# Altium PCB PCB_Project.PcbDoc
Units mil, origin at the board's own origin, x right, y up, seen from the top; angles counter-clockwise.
Board outline 1574.8 x 1574.8 mil, 2 copper layers (Top Layer, Bottom Layer); 30 components, 25 nets, 151 pads, 12 vias.
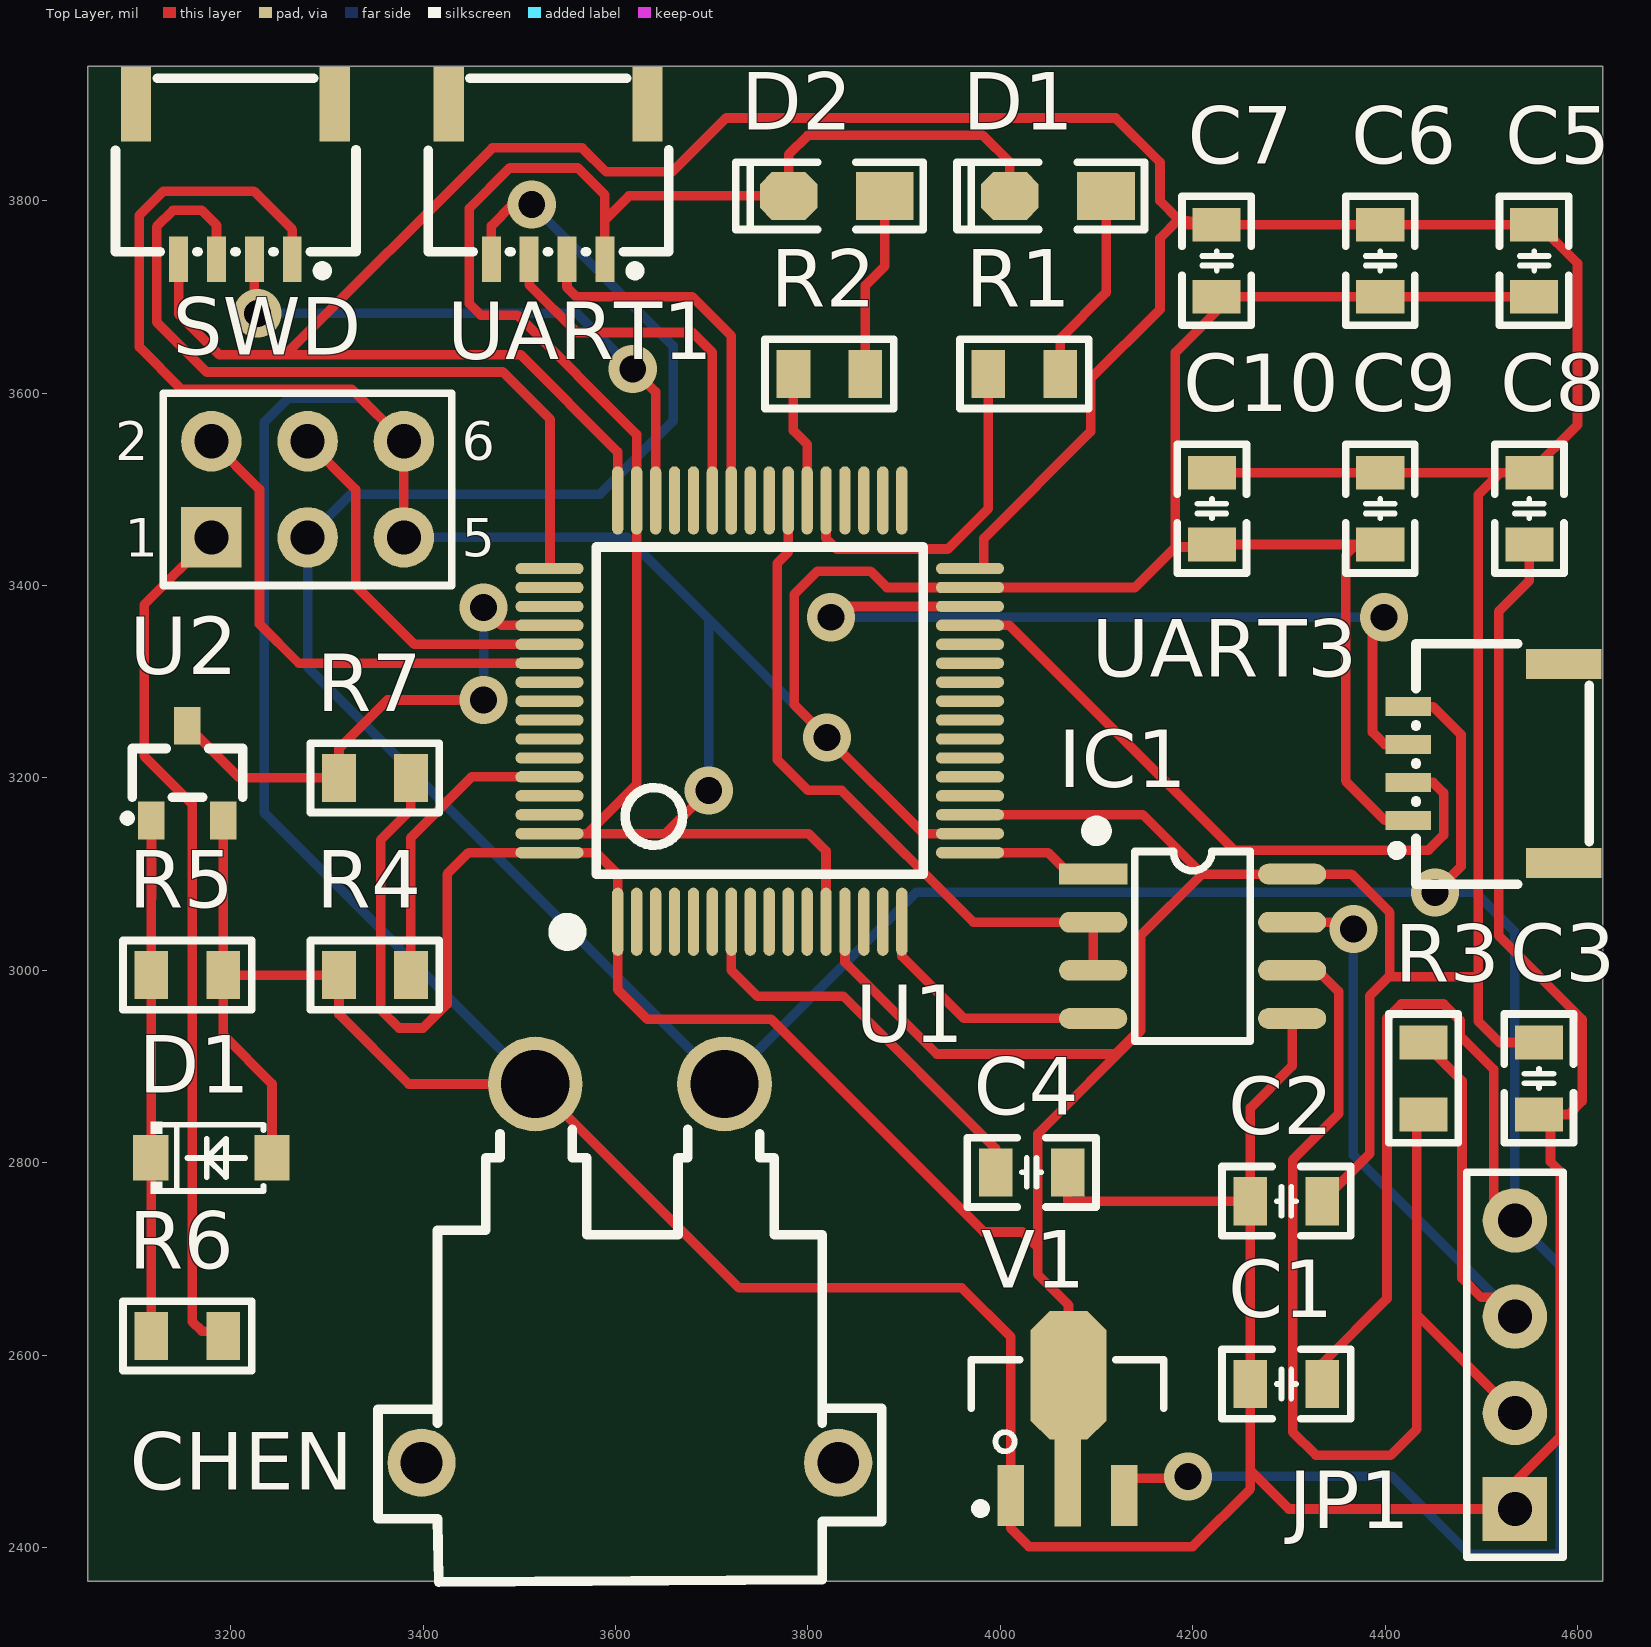
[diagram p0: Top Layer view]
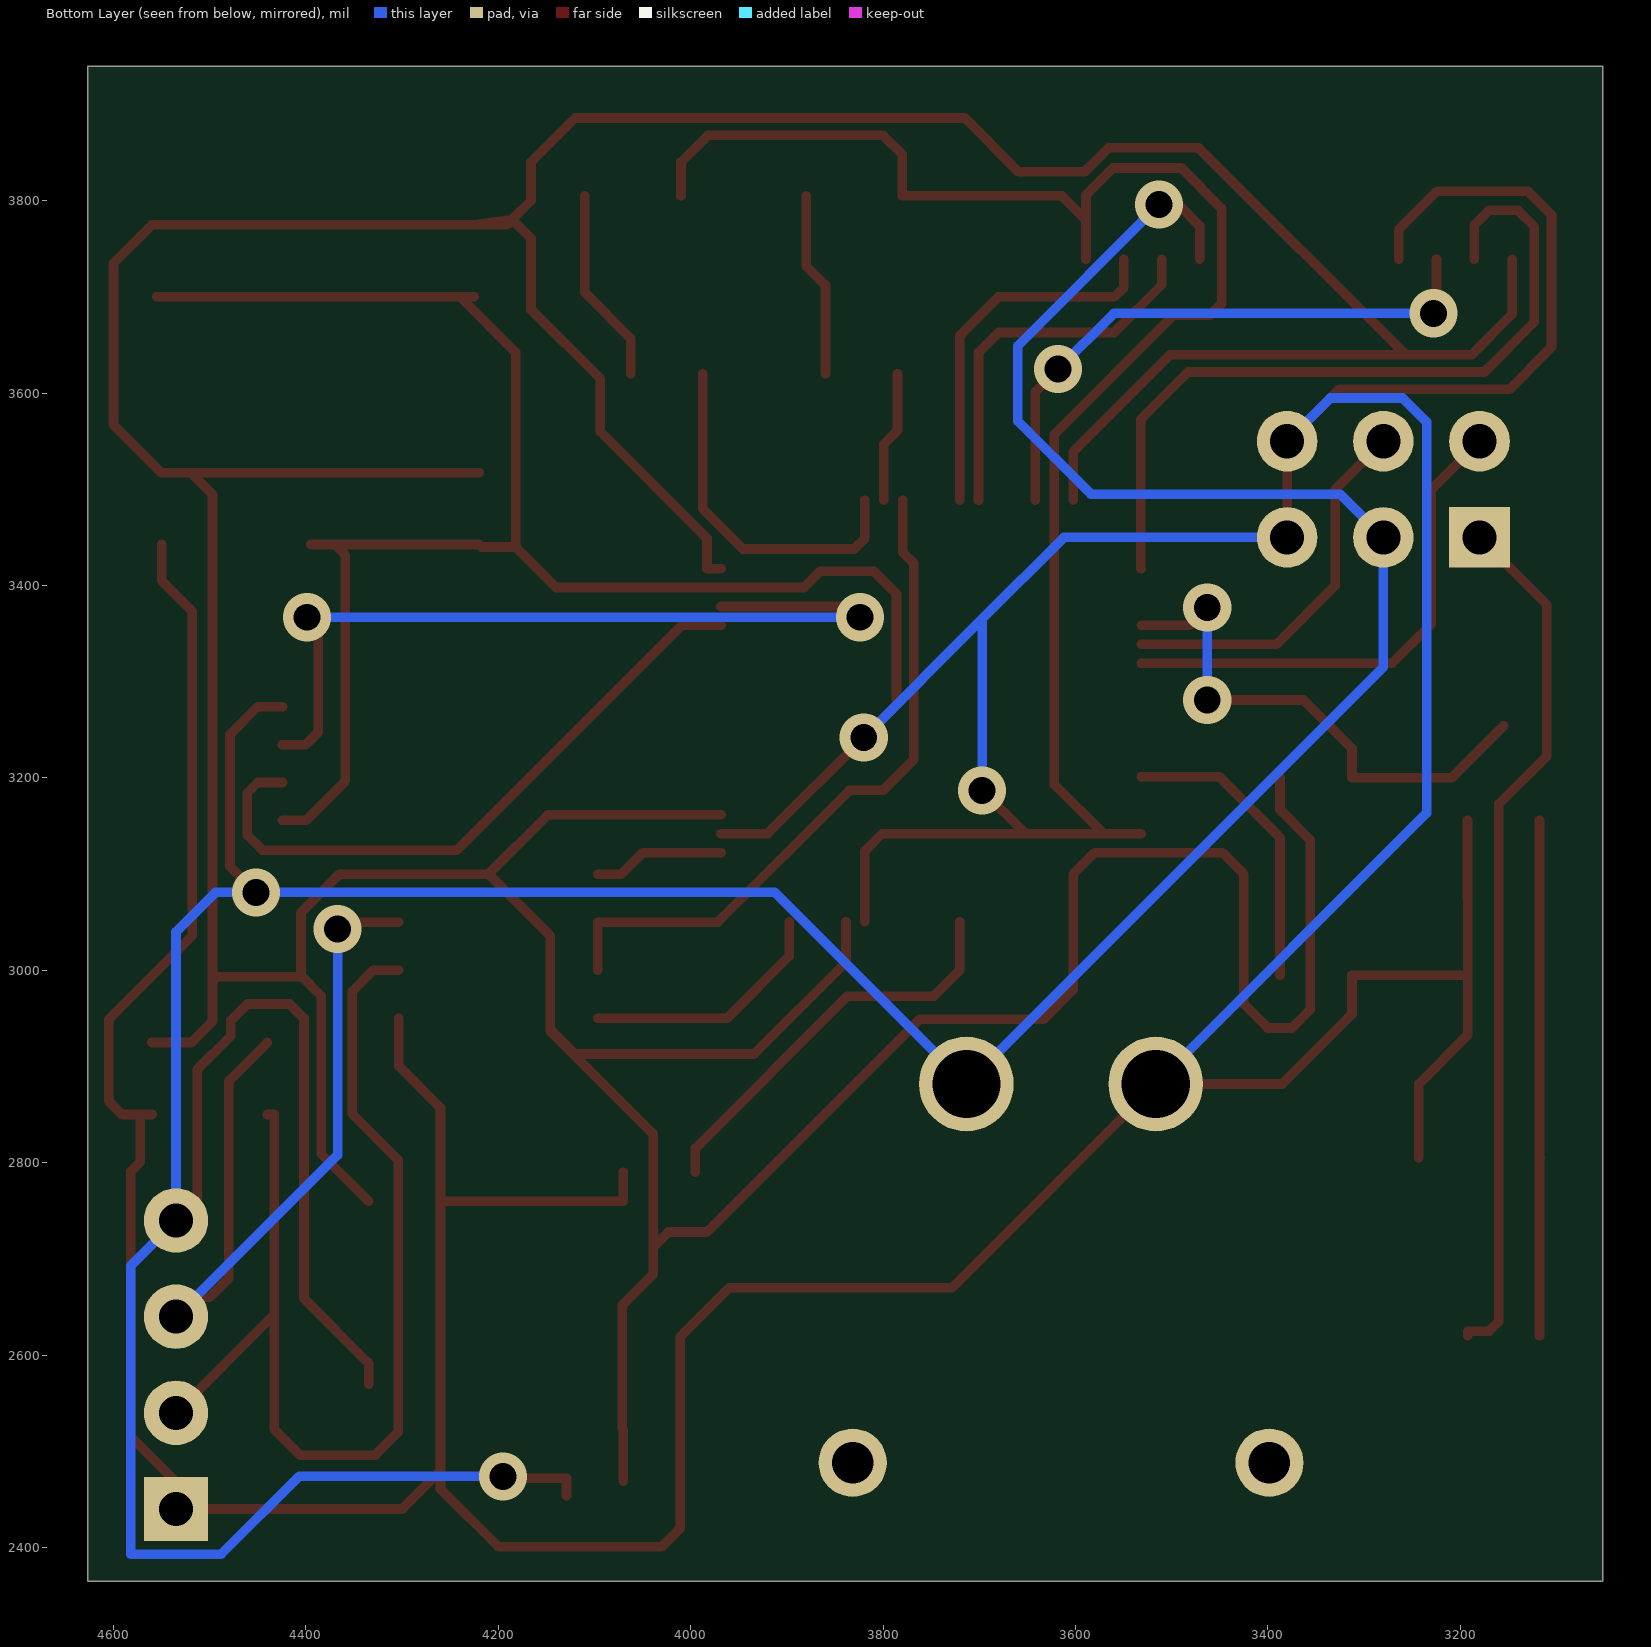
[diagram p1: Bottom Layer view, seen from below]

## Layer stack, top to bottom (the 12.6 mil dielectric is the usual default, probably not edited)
Top Solder: solder mask 0.4, Solder Resist, Dk 3.5
Top Layer: signal copper 1.4
Dielectric 1: dielectric 12.6, FR-4, Dk 4.8
Bottom Layer: signal copper 1.4
Bottom Solder: solder mask 0.4, Solder Resist, Dk 3.5

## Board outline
3051.69,2365.2 3051.69,3940 4626.5,3940 4626.5,2365.2

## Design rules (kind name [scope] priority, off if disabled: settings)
Clearance [All] p1: gap=8 ignorepadtopadclearanceinfootprint=TRUE
PolygonConnect [All] p1: connectstyle=Relief reliefconductorwidth=10 reliefentries=4 polygonreliefangle="90 Angle" airgapwidth=10
RoutingVias [All] p1: holewidth=28 width=50 viastyle="Through Hole" minholewidth=28 minwidth=50 maxholewidth=28 maxwidth=50
SolderMaskExpansion [All] p1: expansion=4
Width [All] p1: maxlimit=10 minlimit=10 preferedwidth=10
30 further rules are at their usual default settings.

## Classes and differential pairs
component class PCB_Project: C1 C2 C3 C4 C5 C6 C7 C8 C9 C10 D1 D2 IC1 JP1 R1 R2 R3 R4 R5 R6 R7 SWD U1 U2 UART1 UART3 V1

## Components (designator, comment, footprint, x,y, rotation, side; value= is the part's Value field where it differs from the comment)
C1 "10uF" "C 0805_L" 4297.4,2570 r0 top
C2 "22uF" "C 0805_L" 4297.4,2760 r0 top
C3 "0.1uF" "C 0805_L" 4560,2887.6 r90 top
C4 "0.1uF" "C 0805_L" 4032.6,2790 r180 top
C5 "0.1uF" "C 0805_L" 4555,3737.6 r90 top
C6 "1uF" "C 0805_L" 4395,3737.6 r90 top
C7 "0.1uF" "C 0805_L" 4225,3737.6 r90 top
C8 "0.1uF" "C 0805_L" 4550,3480 r90 top
C9 "0.1uF" "C 0805_L" 4395,3480 r90 top
C10 "0.1uF" "C 0805_L" 4220,3480 r90 top
CHEN "" CONN-TH_XT30PW-M 3615,2685 r0 top (schematic designator XT30)
D1 "红色" "LED 0805G" 4060,3805 r180 top (schematic designator LED1)
D1 "SMF5.0A" SOD-123FL_L2.8-W1.8-LS3.8-RD 3180,2805 r0 top
D2 "红色" "LED 0805G" 3830,3805 r180 top (schematic designator LED2)
IC1 "SP3485" SOP8_N 4200,3025 r0 top
JP1 "HDR-1X4" HDR2.54-LI-4P 4535,2590 r90 top
JP2 "Header3X2" HDR2.54-LI-2x3P 3280,3500 r0 top
R1 "1K" "R 0805_L" 4025,3620 r0 top
R2 "1K" "R 0805_L" 3822.4,3620 r0 top
R3 "120R" "R 0805_L" 4440,2887.6 r90 top
R4 "1K" "R 0805_L" 3350,2995 r0 top
R5 "5.1k" "R 0805_L" 3155,2995 r180 top
R6 "33R" "R 0805_L" 3155,2620 r0 top
R7 "1k" "R 0805_L" 3350,3200 r0 top
SWD "" CONN-SMD_4P-P1.00_HDGC_HDGC1002WR-S-4P 3205,3820 r180 top
U1 "STM32F103RE" "LQFP64 10X10_N" 3750,3270 r0 top
U2 "BSS138" SOT-23-3_L2.9-W1.3-P1.90-LS2.6-BR 3155.09,3205 r270 top
UART1 "" CONN-SMD_4P-P1.00_HDGC_HDGC1002WR-S-4P 3530,3820 r180 top
UART3 "" CONN-SMD_4P-P1.00_HDGC_HDGC1002WR-S-4P 4505,3215 r90 top
V1 "AMS1117-3V3" SOT89_M 4070,2535 r0 top

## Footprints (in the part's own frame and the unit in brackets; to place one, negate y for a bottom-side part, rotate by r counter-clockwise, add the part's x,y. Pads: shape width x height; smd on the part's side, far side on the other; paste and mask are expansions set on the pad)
"C 0805_L" [mil] "无极性贴片电容"
  rect 35x50 smd: 1(-37.4,0) 2(37.4,0)
  silkscreen extent -67,-36 67,36, body extent -39,-24 39,24, height 20
CONN-SMD_4P-P1.00_HDGC_HDGC1002WR-S-4P [mm]
  rect 0.5x1.2 smd: 1(-1.5,2.05) 2(-0.5,2.05) 3(0.5,2.05) 4(1.5,2.05)
  rect 0.8x2 smd: 5(2.625,-2.05) 6(-2.625,-2.05)
  silkscreen extent -3.18,-2.72 3.17,2.48
CONN-TH_XT30PW-M [mm]
  round 2.5 hole 1.8: 1(-2.5,5) 2(2.5,5)
  round 1.8 hole 1.1: 3(5.5,-5) 4(-5.5,-5)
  silkscreen extent -6.65,-8.15 6.65,3.81
HDR2.54-LI-2x3P [mm] "双排排针，3x2脚"
  rect 1.6x1.6 hole 0.9: 1(-2.54,-1.27)
  round 1.6 hole 0.9: 2(-2.54,1.27) 3(0,-1.27) 4(0,1.27) 5(2.54,-1.27) 6(2.54,1.27)
  silkscreen extent -3.81,-2.54 3.81,2.54, body extent -3.81,-2.54 3.81,2.54, height 8.5
HDR2.54-LI-4P [mm] "排针，4脚"
  rect 1.7x1.7 hole 0.9: 1(-3.81,0)
  round 1.7 hole 0.9: 2(-1.27,0) 3(1.27,0) 4(3.81,0)
  silkscreen extent -5.08,-1.27 5.08,1.27, body extent -5.08,-1.27 5.08,1.27, height 8.5
"LED 0805G" [mil] "绿色0805LED"
  rect 60x50 smd: 1(-50,0)
  oct 60x50 smd: 2(50,0)
  silkscreen extent -90,-35 105,35, body extent -39,-25 39,25, height 32
"LQFP64 10X10_N" [mm] "64脚，体宽10x10mm，脚距0.5mm"
  oval 0.3x1.8 smd: 1(-3.75,-5.575) 2(-3.25,-5.575) 3(-2.75,-5.575) 4(-2.25,-5.575) 5(-1.75,-5.575) 6(-1.25,-5.575) 7(-0.75,-5.575) 8(-0.25,-5.575) 9(0.25,-5.575) 10(0.75,-5.575) 11(1.25,-5.575) 12(1.75,-5.575) 13(2.25,-5.575) 14(2.75,-5.575) 15(3.25,-5.575) 16(3.75,-5.575) 33(3.75,5.55) 34(3.25,5.55) 35(2.75,5.55) 36(2.25,5.55) 37(1.75,5.55) 38(1.25,5.55) 39(0.75,5.55) 40(0.25,5.55) 41(-0.25,5.55) 42(-0.75,5.55) 43(-1.25,5.55) 44(-1.75,5.55) 45(-2.25,5.55) 46(-2.75,5.55) 47(-3.25,5.55) 48(-3.75,5.55)
  oval 1.8x0.3 smd: 17(5.55,-3.75) 18(5.55,-3.25) 19(5.55,-2.75) 20(5.55,-2.25) 21(5.55,-1.75) 22(5.55,-1.25) 23(5.55,-0.75) 24(5.55,-0.25) 25(5.55,0.25) 26(5.55,0.75) 27(5.55,1.25) 28(5.55,1.75) 29(5.55,2.25) 30(5.55,2.75) 31(5.55,3.25) 32(5.55,3.75) 49(-5.55,3.75) 50(-5.55,3.25) 51(-5.55,2.75) 52(-5.55,2.25) 53(-5.55,1.75) 54(-5.55,1.25) 55(-5.55,0.75) 56(-5.55,0.25) 57(-5.55,-0.25) 58(-5.55,-0.75) 59(-5.55,-1.25) 60(-5.55,-1.75) 61(-5.55,-2.25) 62(-5.55,-2.75) 63(-5.55,-3.25) 64(-5.55,-3.75)
  silkscreen extent -5.33,-6.09 4.32,4.32, body extent -6,-6 6,6, height 1.45
"R 0805_L" [mil] "1/8W贴片电阻"
  rect 35x50 smd: 1(-37.4,0) 2(37.4,0)
  silkscreen extent -67,-36 67,36, body extent -39,-25 39,25, height 20
SOD-123FL_L2.8-W1.8-LS3.8-RD [mm]
  rect 0.93x1.2 smd: 1(-1.6,0) 2(1.6,0)
  silkscreen extent -1.6,-0.95 1.38,0.95
SOP8_N [mm] "5*6*1.8mm（长宽高）"
  rect 1.8x0.55 smd: 1(-2.625,1.905)
  oval 1.8x0.55 smd: 2(-2.625,0.635) 3(-2.625,-0.635) 4(-2.625,-1.905) 5(2.625,-1.905) 6(2.625,-0.635) 7(2.625,0.635) 8(2.625,1.905)
  silkscreen extent -2.69,-2.5 1.52,3.2, body extent -3,-2.5 3,2.5, height 1.9
SOT89_M [mm] "4.6x4.3x1.6mm(长宽高)"
  rect 0.7x1.6 smd: 1(-1.5,-2.054) 3(1.5,-2.054)
  rect 0.7x2.4 smd: 2(0,-1.676)
  oct 2x3.4 smd: 2(0.025,1.118)
  silkscreen extent -2.54,-2.52 2.54,1.52, body extent -2.3,-2.4 2.3,1.9, height 1.6
SOT-23-3_L2.9-W1.3-P1.90-LS2.6-BR [mm]
  rect 1x0.7 smd: 1(1.25,-0.95) 2(1.25,0.95) 3(-1.25,0)
  silkscreen extent -0.65,-1.69 1.29,1.46

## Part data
C1 C2 C3 C4 C5 C6 C7 C8 C9 C10: library part C, "无极性贴片电容"
CHEN: library part XT30PW-M, BOM_JLCPCB Part Class="Extended Part", BOM_Manufacturer="Changzhou Amass Elec"
D1 D2: library part LED-SMD, "贴片LED"
D1: library part SMF5.0A_C2836403, BOM_JLCPCB Part Class="Extended Part", BOM_Manufacturer=MSKSEMI(美森科)
IC1: "RS485总线收发芯片"
JP1: library part "Header 4", "4P接插件"
JP2: library part "Header 3X2", "3*2P接插件"
R1 R2 R3 R4 R5 R6 R7: library part R, "贴片电阻"
SWD UART1 UART3: library part HDGC1002WR-S-4P, BOM_JLCPCB Part Class="Extended Part", BOM_Manufacturer=HDGC(华德共创)
U1: "32位STM单片机"
U2: library part BSS138_C3015220, BOM_Manufacturer=KUU
V1: library part AMS1117, "三端稳压芯片"

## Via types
v1: diameter 50, hole 28, Top Layer to Bottom Layer, 12 vias

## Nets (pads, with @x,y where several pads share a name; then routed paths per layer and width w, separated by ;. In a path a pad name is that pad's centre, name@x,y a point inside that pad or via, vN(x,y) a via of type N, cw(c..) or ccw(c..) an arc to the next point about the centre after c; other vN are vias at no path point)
485A: IC1.6 JP1.2 R3.1 | length 1164
  Top Layer w10: IC1.6 4330,3000 4351.78,2978.22 4351.78,2850.78 4304,2803 4304,2520 4328,2496 4406,2496 4433,2523 4433,2642 ; R3.1 4433,2850.2 4433,2642 ; JP1.2 4433,2642
485B: IC1.7 JP1.3 R3.2 | length 884
  Top Layer w10: IC1.7 4360,3050 v1(4367,3043) ; R3.2 4480,2885 4480,2680 4500,2660 4535,2660 JP1.3
  Bottom Layer w10: v1(4367,3043) 4367,2808 JP1.3
485RE: IC1.2 IC1.3 U1.39 | length 722.9
  Top Layer w10: U1.39 3779.53,3434.53 3768,3423 3768,3219 3800,3187 3835,3187 3972,3050 IC1.2 IC1.3
+5: C1.2 CHEN.2 JP1.4 JP2.3 UART1.4 UART3.4 V1.3 | length 4625.7
  Top Layer w10: UART1.4 3470.95,3773.95 3493,3796 v1(3513,3796) ; V1.3 4129.06,2472 4193,2472 v1(4195,2474) ; C1.2 4334.8,2591.56 4402,2658.76 4402,2950 4417,2965 4460.88,2965 4478,2947.88 4478,2932 4513,2897 4513,2740 JP1.4 ; UART3.4 4450,3274.05 4478.92,3245.13 4478.92,3107.92 v1(4452,3081)
  Bottom Layer w10: v1(3513,3796) 3660,3649 3660,3571 3584,3495 3325,3495 JP2.3 3280,3315.27 CHEN.2 3912.57,3081 v1(4452,3081) 4494,3081 4535,3040 JP1.4 4582,2693 4582,2393 4488,2393 4407,2474 v1(4195,2474)
GND: C1.1 C2.1 C3.1 C4.1 C5.1 C6.1 C7.1 C8.1 C9.1 C10.1 CHEN.1 D1.2 D2.2 IC1.5 JP1.1 JP2.5 JP2.6 R4.1 R5.1 SWD.1 U1.12 U1.18 U1.31 U1.47 U1.63 U2.2 UART1.1 UART3.1 V1.1 | length 10341.2
  Top Layer w10: U2.2 3192.49,3075.08 3192.4,3075 R5.1 ; D1.2@3242.99,2805 3242.99,2882.01 3192.4,2932.6 R5.1 ; SWD.1 3264.06,3770 3224.06,3810 3130,3810 3105.11,3785.11 3105.11,3647.89 3149,3604 3326,3604 JP2.6 JP2.5 ; U1.63 3571,3142.05 ; UART1.1 3589.06,3780 ; v1(3697,3187) 3652.05,3142.05 ; U1.12 3818.9,3124 3800.85,3142.05 3652.05,3142.05 ; U1.18 3920,3142.05 v1(3820.05,3242) 3786,3276.05 3786,3391 3810,3415 3865,3415 3882.05,3397.95 U1.31 4139.95,3397.95 4182,3440 ; D1.2@4010,3805 4010,3840 3982,3868 3800,3868 3780,3848 D2.2 3614.06,3805 3589.06,3780 ; C4.1 4070,2760 C2.1 ; C7.1 C7.1@4240,3700.2 ; IC1.5 4303.35,2900.35 4260,2857 C2.1 ; C9.1 4370,3442.6 ; UART3.1 4400,3155.94 4359,3196.94 4359,3431.6 4370,3442.6 ; C8.1 4550,3405 4518,3373 4518,3036 4605,2949 4605,2864.2 4591,2850.2 C3.1@4572,2850.2 ; C5.1 C6.1 C7.1@4240,3700.2 ; C3.1 C3.1@4572,2850.2 ; R5.1 3252,2995 R4.1 3312.6,2954.4 3385.15,2881.85 CHEN.1 3728.42,2670 3960,2670 4010.94,2619.06 V1.1 4010.94,2420 4029.94,2401 4200,2401 4260,2461 4260,2480 ; 3571,3142.05 3652.05,3142.05 ; 3571,3142.05 3622.05,3193.1 U1.47 3622.05,3556.95 3498,3681 3460,3681 3448,3693 3448,3792 3490,3834 3561,3834 3589.06,3805.94 3589.06,3780 ; 4182,3440 4217.41,3440 C10.1 4370,3442.6 ; 4182,3440 4182,3642.2 C7.1@4240,3700.2 ; 4260,2480 C1.1 C2.1 ; 4260,2480 4300,2440 JP1.1 4535,2468 4582,2515 4582,2791 4572,2801 C3.1@4572,2850.2
  Bottom Layer w10: JP2.5 3612.05,3450 3697,3365.05 ; JP2.6 3335,3595 3260,3595 3235,3570 3235,3163.42 CHEN.1 ; v1(3697,3187) 3697,3365.05 ; v1(3820.05,3242) 3697,3365.05
NetC4_2: C4.2 U1.7 | length 426.7
  Top Layer w10: U1.7 3720.47,3000 3747.28,2973.2 3836.8,2973.2 3995.2,2814.8 C4.2
NetD1_1: D1.1@3117.01,2805 R5.2 R6.1 U2.1 | length 536.3
  Top Layer w10: R6.1 3117.6,2804.41 3117.01,2805 3117.6,2805.6 R5.2 3117.6,3075 3117.69,3075.08 U2.1
NetLED1_1: D1.1@4110,3805 R1.2 | length 204.7
  Top Layer w10: R1.2 4062.4,3657 4110,3704.6 D1.1@4110,3805
NetLED2_1: D2.1 R2.2 | length 193.4
  Top Layer w10: R2.2 3859.8,3712 3880,3732.2 D2.1
NetR1_1: R1.1 U1.37 | length 370.1
  Top Layer w10: U1.37 3818.9,3449.1 3830,3438 3945.6,3438 3987.6,3480 R1.1
NetR2_1: R2.1 U1.38 | length 137.4
  Top Layer w10: R2.1 3785,3561.21 3799.21,3547 U1.38
NetR4_2: R4.2 U1.60 | length 313.2
  Top Layer w10: R4.2 3387.4,3138 3450.5,3201.1 U1.60
RX1: U1.43 UART1.3 | length 400
  Top Layer w10: UART1.3 3510.32,3712.68 3560,3663 3680,3663 3700.79,3642.21 U1.43
RX2: IC1.1 U1.17 | length 137.4
  Top Layer w10: U1.17 4049.64,3122.36 4072,3100 IC1.1
RX3: U1.30 UART3.3 | length 891.1
  Top Layer w10: v1(3824,3367) 3835.27,3378.27 U1.30 ; v1(4399,3367) 4387,3355 4387,3247.68 4400,3234.68 UART3.3
  Bottom Layer w10: v1(3824,3367) v1(4399,3367)
RX4: R7.1 U1.52 U2.3 | length 554
  Top Layer w10: U2.3 3209.29,3200 R7.1 3312.6,3230.6 3363,3281 v1(3463,3281) ; v1(3463,3377) 3481.42,3358.58 U1.52
  Bottom Layer w10: v1(3463,3281) v1(3463,3377)
RX5: JP2.2 U1.54 | length 529.1
  Top Layer w10: JP2.2 3230,3500 3230,3360 3270.79,3319.21 U1.54
SBUS: JP2.1 R6.2 | length 906.2
  Top Layer w10: JP2.1 3110,3380 3110,3223 3160,3173 3160,2635 3170,2625 3192.4,2625 R6.2
SWC: SWD.3 U1.49 | length 816.7
  Top Layer w10: SWD.3 3185.32,3774.68 3170,3790 3140,3790 3123.11,3773.11 3123.11,3673.89 3175,3622 3483,3622 3532,3573 3532,3417.64 U1.49
SWD: SWD.2 U1.46 | length 618
  Top Layer w10: SWD.2 3224.69,3686.31 v1(3228,3683) ; v1(3618,3625) 3641.73,3601.27 U1.46
  Bottom Layer w10: v1(3228,3683) 3560,3683 v1(3618,3625)
TX1: U1.42 UART1.2 | length 392
  Top Layer w10: UART1.2 3549.69,3710 3559.69,3700 3680,3700 3720.47,3659.53 U1.42
TX2: IC1.4 U1.16 | length 261.7
  Top Layer w10: U1.16 3897.64,3014.63 3962.27,2950 IC1.4
TX3: U1.29 UART3.2 | length 680.5
  Top Layer w10: U1.29 4009.42,3358.58 4243,3125 4445.2,3125 4460.92,3140.71 4460.92,3184.39 4450,3195.31 UART3.2
TX5: JP2.4 U1.53 | length 397.5
  Top Layer w10: JP2.4 3330,3500 3330,3400 3391.1,3338.9 U1.53
VCC_3.3: C2.2 C3.2 C5.2 C6.2 C7.2 C8.2 C9.2 C10.2 IC1.8 R7.2 SWD.4 U1.1 U1.13 U1.19 U1.32 U1.48 U1.64 V1.2 | length 7247.1
  Top Layer w10: SWD.4 3145.95,3682.05 3188,3640 3257,3640 ; R7.2 3387.4,3167 3356,3135.6 3356,2959 3375,2940 3400,2940 3425,2965 3425,3100 3447.36,3122.36 U1.64 3580,3122.36 3602.36,3100 U1.1 3602.36,2980 3633.36,2949 3762,2949 3983,2728 4023,2728 4039,2712 ; U1.48 3602.36,3539 3501.36,3640 3257,3640 ; U1.13 3838.58,3008.42 3934,2913 4120,2913 4146,2939 ; U1.19 4148.27,3161.73 4210,3100 ; U1.32 3983,3417.64 3983,3449 4094,3560 4094,3615 4166,3687 4166,3761 4185.5,3780.5 ; V1.2@4070,2469 4070,2523 4071,2524 4071,2579 4071,2652 4039,2684 4039,2712 ; 4191.65,3779.64 C7.2 ; C10.2 C9.2 4520,3517.4 ; C2.2 4384,2809.2 4384,2973.5 4405,2994.5 ; 4497,2990 4497,3494.4 4520,3517.4 ; C3.2 4519,2925 4497,2947 4497,2988.68 4492.5,2993.18 4405,2993.18 4405,2994.5 ; 3257,3640 3472,3855 3565.46,3855 3590.46,3830 3659,3830 3715,3886 4120,3886 4166,3840 4166,3800 4185.5,3780.5 ; 4039,2712 4039,2830 4146,2937 4146,2939 ; 4146,2939 4146,3036 4210,3100 ; 4185.5,3780.5 4191,3775 C7.2 ; 4210,3100 IC1.8 4365,3100 4405,3060 4405,2994.5 ; C7.2 C6.2 C5.2 4560,3775 4600,3735 4600,3567 4550.4,3517.4 C8.2 4520,3517.4
pads on no net: CHEN.3 CHEN.4 SWD.5 SWD.6 U1.2 U1.3 U1.4 U1.5 U1.6 U1.8 U1.9 U1.10 U1.11 U1.14 U1.15 U1.20 U1.21 U1.22 U1.23 U1.24 U1.25 U1.26 U1.27 U1.28 U1.33 U1.34 U1.35 U1.36 U1.40 U1.41 U1.44 U1.45 U1.50 U1.51 U1.55 U1.56 U1.57 U1.58 U1.59 U1.61 U1.62 UART1.5 UART1.6 UART3.5 UART3.6

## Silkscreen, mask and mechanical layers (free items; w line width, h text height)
Mechanical 13:
  the board outline again, w10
